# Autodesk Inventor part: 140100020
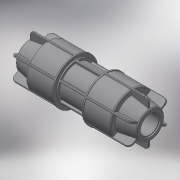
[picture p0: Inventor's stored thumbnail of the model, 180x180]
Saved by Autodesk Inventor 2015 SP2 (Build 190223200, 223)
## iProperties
Created: 2018-02
Part Number: 140100020
Material: Generic
Description: PLASSON L.14 COUPLER (SILVER) 20
Document SubType Name: Modeling
Designer: KIM
Mass: 67.3842 g
Surface Area: 206.511 cm^2
Volume: 67.3842 cm^3
Density: 1 g/cm^3
Appearance: Default
Author: KIM
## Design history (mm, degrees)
derived "140100.ipt"
feature "Solid1::140100.ipt"
tag "TaggingFeature1"
body "Solid1"
other parameters: "d30" = 1, "d36" = 0.9, "d65" = 40.74, "d77" = 18.4, "d95" = 13.5, "d96" = 0.9, "d97" = 22, "d100" = 31.5, "d102" = 34.2, "d103" = 0.9, "d107" = 62.65, "d113" = 42, "d114" = 2, "d115" = 1, "d117" = 0, "d126" = 4.2, "d127" = 0.42, "d129" = 360 deg, "d131" = 0.9, "d132" = 42, "d138" = 100 deg, "d139" = 35.7, "d143" = 44, "d144" = 0, "d146" = 44, "d147" = 0, "d149" = 2.1, "d150" = 1.05, "d152" = 0, "d153" = 0.42, "d155" = 360 deg, "E_" = 42, "l_" = 44
